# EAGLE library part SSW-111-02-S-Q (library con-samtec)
THROUGH-HOLE .025" SQ POST SOCKET Source: Samtec SSW.pdf
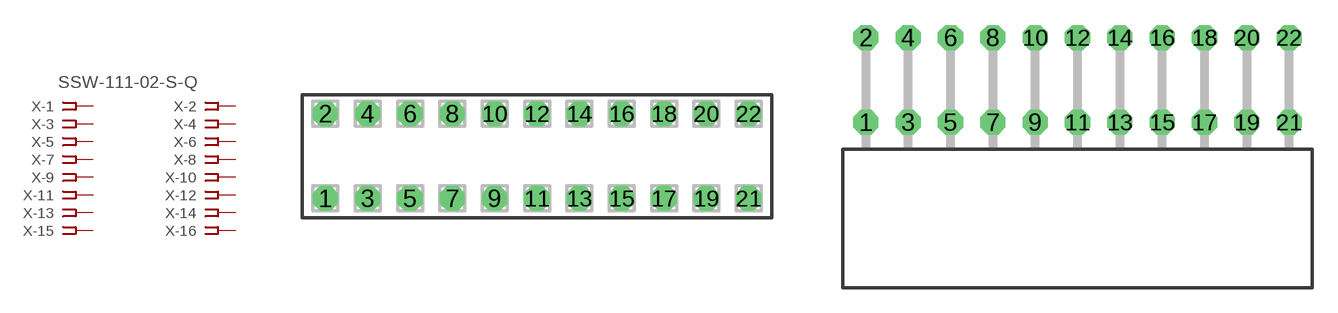
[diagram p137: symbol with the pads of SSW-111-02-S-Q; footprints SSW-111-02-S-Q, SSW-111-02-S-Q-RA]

Designator prefix X; gates -1=FPINV -2=FPIN -3=FPIN -4=FPIN -5=FPIN -6=FPIN -7=FPIN -8=FPIN -9=FPIN -10=FPIN -11=FPIN -12=FPIN -13=FPIN -14=FPIN -15=FPIN -16=FPIN -17=FPIN -18=FPIN -19=FPIN -20=FPIN -21=FPIN -22=FPIN

## SSW-111-02-S-Q (OC_FARNELL: unknown; OC_NEWARK: unknown)  [SSW-111-02-S-Q]
1  -1:1  pas
2  -2:1  pas
3  -3:1  pas
4  -4:1  pas
5  -5:1  pas
6  -6:1  pas
7  -7:1  pas
8  -8:1  pas
9  -9:1  pas
10  -10:1  pas
11  -11:1  pas
12  -12:1  pas
13  -13:1  pas
14  -14:1  pas
15  -15:1  pas
16  -16:1  pas
17  -17:1  pas
18  -18:1  pas
19  -19:1  pas
20  -20:1  pas
21  -21:1  pas
22  -22:1  pas

## SSW-111-02-S-QRA (OC_FARNELL: unknown; OC_NEWARK: unknown)  [SSW-111-02-S-Q-RA]
Pads as for SSW-111-02-S-Q

## Footprint SSW-111-02-S-Q (pad centres in mm)
THROUGH-HOLE .025" SQ POST SOCKET Source: Samtec SSW.pdf
drill 1 pad 1.5 octagon: 1 -12.7,-2.54; 2 -12.7,2.54; 3 -10.16,-2.54; 4 -10.16,2.54; 5 -7.62,-2.54; 6 -7.62,2.54; 7 -5.08,-2.54; 8 -5.08,2.54; 9 -2.54,-2.54; 10 -2.54,2.54; 11 0,-2.54; 12 0,2.54; 13 2.54,-2.54; 14 2.54,2.54; 15 5.08,-2.54; 16 5.08,2.54; 17 7.62,-2.54; 18 7.62,2.54; 19 10.16,-2.54; 20 10.16,2.54; 21 12.7,-2.54; 22 12.7,2.54

## Footprint SSW-111-02-S-Q-RA (pad centres in mm)
THROUGH-HOLE .025" SQ POST SOCKET Source: Samtec SSW.pdf
drill 1 pad 1.5 octagon: 1 -12.7,1.524; 2 -12.7,6.604; 3 -10.16,1.524; 4 -10.16,6.604; 5 -7.62,1.524; 6 -7.62,6.604; 7 -5.08,1.524; 8 -5.08,6.604; 9 -2.54,1.524; 10 -2.54,6.604; 11 0,1.524; 12 0,6.604; 13 2.54,1.524; 14 2.54,6.604; 15 5.08,1.524; 16 5.08,6.604; 17 7.62,1.524; 18 7.62,6.604; 19 10.16,1.524; 20 10.16,6.604; 21 12.7,1.524; 22 12.7,6.604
